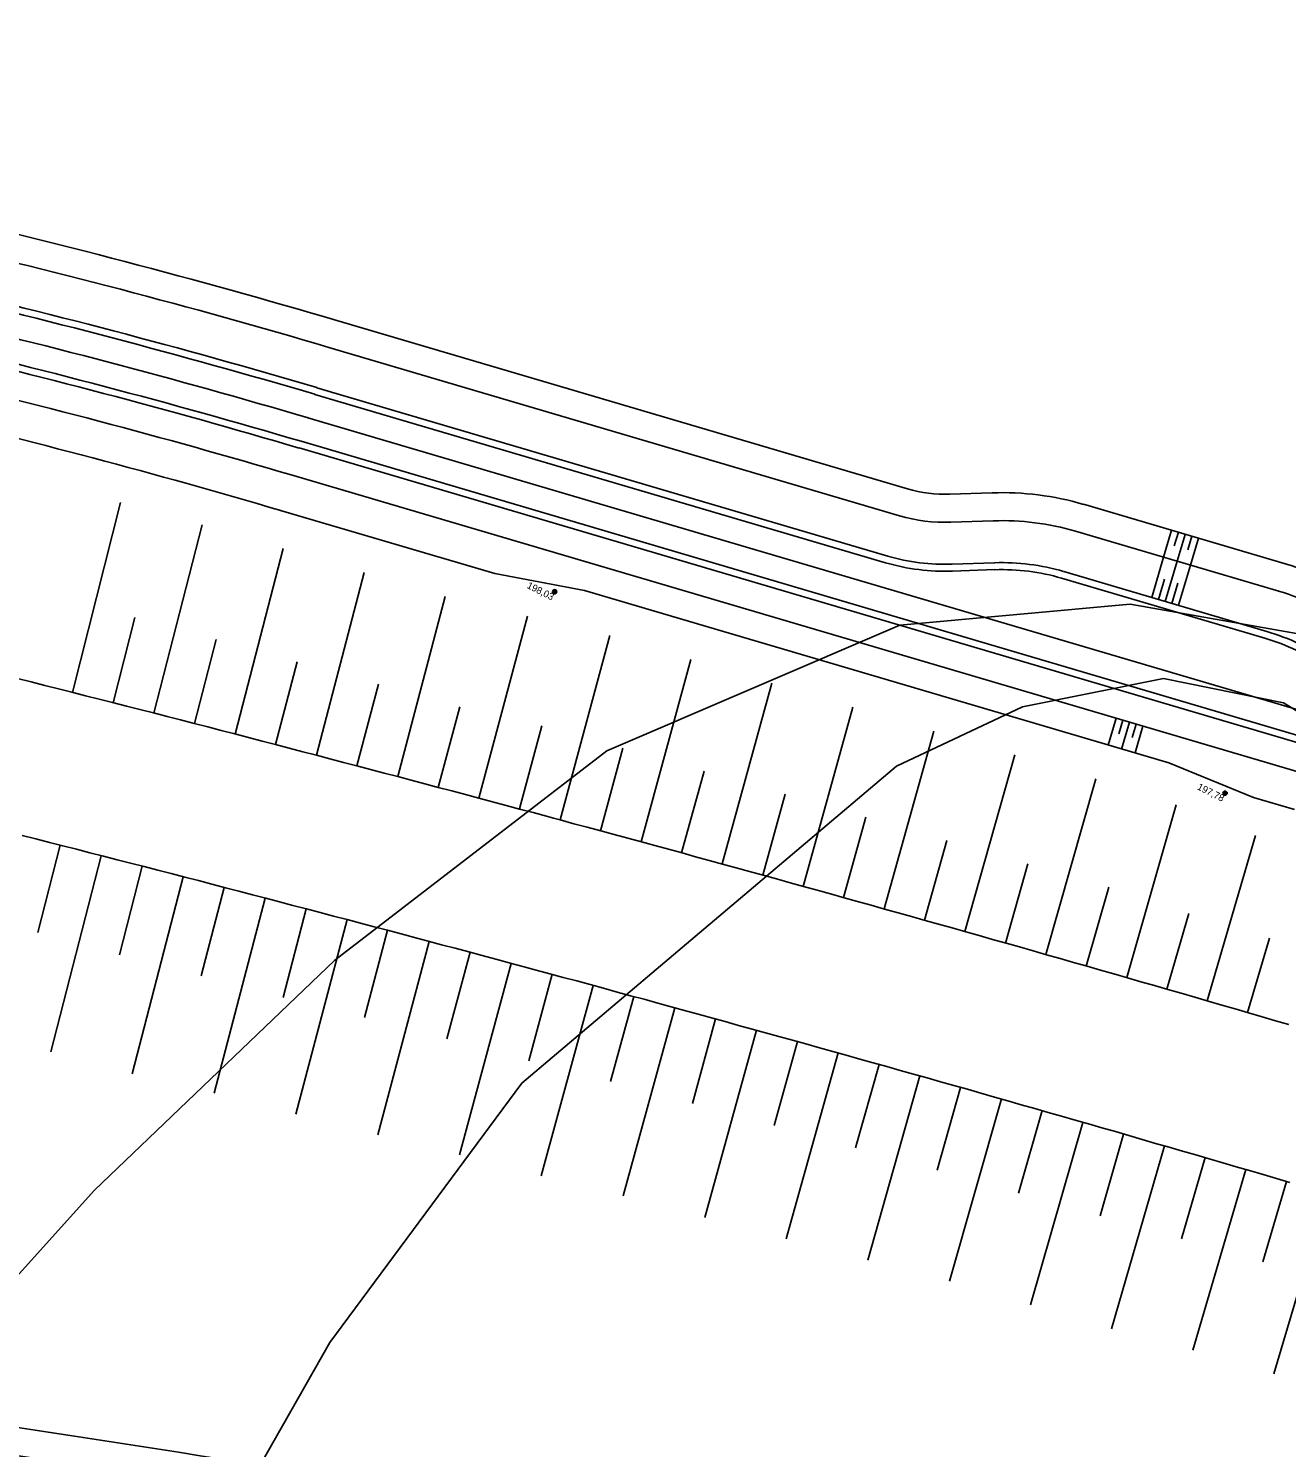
# Model space of a CAD drawing. Extents: x -551750 to -547457, y -1150683 to -1148508.
# Drawn here: x -551001.9 to -550912.1, y -1148784.8 to -1148683.4 of the extents above; entities that cross this region are included whole.
import ezdxf

# ---------------------------------------------------------------- set-up
doc = ezdxf.new("R2010")
doc.units = 0
for name, color, linetype in [('D02_ZaplUzemi20Vody', 7, 'Continuous'), ('D03_ZaplUzemi100Vody', 7, 'Continuous'), ('SO221815_VYSKOPIS', 7, 'Continuous'), ('u_trat navrh', 7, 'Continuous')]:
    doc.layers.add(name, color=color, linetype=linetype)

# ---------------------------------------------------------------- blocks, each defined once
blk = doc.blocks.new('SO221824_VYSKOPIS')
at = {"layer": 'SO221815_VYSKOPIS'}
for p, q in [((0.12, -0.09), (-0.12, 0.09)), ((0.09, 0.12), (-0.09, -0.12)), ((0.09, 0.12), (0, 0)), ((0, 0), (0.12, -0.09))]:
    blk.add_line(p, q, dxfattribs=at)
blk.add_lwpolyline([(-0.09, -0.12), (0, 0), (-0.12, 0.09)], dxfattribs=at)
blk.add_circle((0, 0), 0.15, dxfattribs=at)
for start, end in [(145.362, 235.1538), (325.362, 55.1538)]:
    blk.add_arc((0, 0), 0.15, start, end, dxfattribs=at)

msp = doc.modelspace()

# ---------------------------------------------------------------- linework, layer by layer
at = {"layer": 'D02_ZaplUzemi20Vody'}
msp.add_lwpolyline([(-551109.36, -1148705.24), (-551088.1, -1148709.36), (-551068.89, -1148720.34), (-551055.18, -1148738.19), (-551046.26, -1148762.89), (-551042.14, -1148808.19), (-551041.54, -1148830.24), (-551039.22, -1148846.5), (-551035.97, -1148860.35), (-551032.72, -1148862.74), (-551027.74, -1148863.09), (-551023.25, -1148861.46), (-551020.88, -1148856.92), (-551011.96, -1148833.58), (-551000.3, -1148812.31), (-550980.41, -1148777.31), (-550966.69, -1148758.78), (-550939.94, -1148736.13), (-550930.94, -1148731.89), (-550920.87, -1148729.87), (-550912.3, -1148731.6), (-550896.22, -1148741.39)], dxfattribs=at)
at = {"layer": 'D03_ZaplUzemi100Vody'}
msp.add_lwpolyline([(-551309.02, -1148785.89), (-551249.96, -1148750.74), (-551230.63, -1148737.06), (-551208, -1148722.96), (-551182.79, -1148711.42), (-551146.06, -1148694.75), (-551122.83, -1148687.16), (-551095.92, -1148683.42), (-551079.48, -1148686.41), (-551056.31, -1148700.62), (-551045.84, -1148714.09), (-551036.12, -1148737.27), (-551031.64, -1148755.22), (-551029.4, -1148770.93), (-551025.66, -1148778.41), (-551019.68, -1148783.65), (-551014.11, -1148783.92), (-551010.71, -1148781.4), (-550997.25, -1148766.44), (-550980.06, -1148749.99), (-550960.63, -1148735.03), (-550939.7, -1148726.05), (-550923.25, -1148724.56), (-550910.54, -1148726.8)], dxfattribs=at)
at = {"layer": 'u_trat navrh'}
for p, q in [((-550979.91, -1148704.29), (-550939.15, -1148716.32)), ((-550980.48, -1148706.21), (-550939.72, -1148718.24)), ((-550981.33, -1148709.09), (-550940.56, -1148721.12)), ((-550981.47, -1148709.57), (-550940.71, -1148721.6)), ((-550981.97, -1148711.25), (-550909.55, -1148732.61)), ((-550982.46, -1148712.92), (-550910.05, -1148734.29)), ((-550982.6, -1148713.4), (-550910.19, -1148734.77)), ((-550983.17, -1148715.32), (-550910.76, -1148736.69)), ((-550936.13, -1148716.7), (-550933.09, -1148716.6)), ((-550998.8, -1148730.86), (-550995.35, -1148717.29)), ((-550983.92, -1148717.86), (-550968.63, -1148722.37)), ((-550926.58, -1148717.42), (-550912.07, -1148721.71)), ((-550992.98, -1148732.34), (-550989.53, -1148718.9)), ((-550936.06, -1148718.7), (-550933.02, -1148718.6)), ((-550927.15, -1148719.34), (-550912.63, -1148723.62)), ((-550920.85, -1148721.2), (-550920.28, -1148719.28)), ((-550920.09, -1148720.38), (-550919.8, -1148719.42)), ((-550919.89, -1148721.48), (-550919.32, -1148719.57)), ((-550919.13, -1148720.67), (-550918.84, -1148719.71)), ((-550918.93, -1148721.77), (-550918.36, -1148719.85)), ((-550987.17, -1148733.84), (-550983.74, -1148720.59)), ((-550921.7, -1148724.08), (-550920.85, -1148721.2)), ((-550981.37, -1148735.35), (-550977.96, -1148722.29)), ((-550935.96, -1148721.7), (-550932.92, -1148721.6)), ((-550935.94, -1148722.2), (-550932.9, -1148722.09)), ((-550927.99, -1148722.22), (-550913.48, -1148726.5)), ((-550920.74, -1148724.36), (-550919.89, -1148721.48)), ((-550919.78, -1148724.64), (-550918.93, -1148721.77)), ((-550968.63, -1148722.37), (-550962.22, -1148723.59)), ((-550928.14, -1148722.7), (-550913.62, -1148726.98)), ((-550921.22, -1148724.22), (-550920.79, -1148722.78)), ((-550920.26, -1148724.5), (-550919.83, -1148723.06)), ((-550975.56, -1148736.88), (-550972.16, -1148724)), ((-550962.22, -1148723.59), (-550920.49, -1148735.9)), ((-550995.89, -1148731.6), (-550994.34, -1148725.52)), ((-550969.76, -1148738.42), (-550966.3, -1148725.42)), ((-550990.08, -1148733.09), (-550988.53, -1148727.08)), ((-550963.96, -1148739.97), (-550960.41, -1148726.79)), ((-550984.28, -1148734.59), (-550982.74, -1148728.67)), ((-550958.17, -1148741.54), (-550954.63, -1148728.5)), ((-550978.47, -1148736.11), (-550976.93, -1148730.28)), ((-550952.38, -1148743.12), (-550948.84, -1148730.21)), ((-550972.66, -1148737.65), (-550971.13, -1148731.89)), ((-550946.6, -1148744.72), (-550943.05, -1148731.91)), ((-550966.86, -1148739.19), (-550965.27, -1148733.25)), ((-550924.24, -1148732.71), (-550924.81, -1148734.63)), ((-550923.76, -1148732.85), (-550924.05, -1148733.81)), ((-550923.29, -1148732.99), (-550923.85, -1148734.91)), ((-550922.81, -1148733.13), (-550923.09, -1148734.09)), ((-550922.33, -1148733.28), (-550922.89, -1148735.19)), ((-550940.81, -1148746.33), (-550937.26, -1148733.62)), ((-550961.07, -1148740.75), (-550959.47, -1148734.85)), ((-550935.04, -1148747.95), (-550931.48, -1148735.33)), ((-550955.28, -1148742.33), (-550953.68, -1148736.49)), ((-550920.49, -1148735.9), (-550914.44, -1148738.36)), ((-550929.26, -1148749.59), (-550925.69, -1148737.04)), ((-550949.49, -1148743.92), (-550947.89, -1148738.13)), ((-550914.44, -1148738.36), (-550911.51, -1148739.23)), ((-550923.49, -1148751.24), (-550919.95, -1148738.89)), ((-550943.71, -1148745.52), (-550942.11, -1148739.78)), ((-550937.93, -1148747.14), (-550936.33, -1148741.44)), ((-550917.73, -1148752.9), (-550914.3, -1148741.08)), ((-550999.68, -1148741.78), (-551001.27, -1148748.01)), ((-550996.75, -1148742.53), (-551000.33, -1148756.54)), ((-550993.81, -1148743.28), (-550995.44, -1148749.62)), ((-550932.15, -1148748.77), (-550930.55, -1148743.1)), ((-550990.88, -1148744.03), (-550994.52, -1148758.11)), ((-550987.95, -1148744.8), (-550989.59, -1148751.1)), ((-550985.02, -1148745.56), (-550988.66, -1148759.5)), ((-550926.38, -1148750.41), (-550924.77, -1148744.78)), ((-550982.09, -1148746.33), (-550983.75, -1148752.66)), ((-550979.17, -1148747.09), (-550982.84, -1148761)), ((-550920.61, -1148752.07), (-550919.05, -1148746.65)), ((-550976.28, -1148747.86), (-550977.93, -1148754.09)), ((-550973.31, -1148748.65), (-550976.99, -1148762.46)), ((-550914.85, -1148753.74), (-550913.3, -1148748.43)), ((-550970.38, -1148749.43), (-550972.04, -1148755.62)), ((-550967.46, -1148750.22), (-550971.15, -1148763.91)), ((-550964.53, -1148751), (-550966.2, -1148757.18)), ((-550961.61, -1148751.8), (-550965.31, -1148765.39)), ((-550958.69, -1148752.59), (-550960.35, -1148758.66)), ((-550955.77, -1148753.39), (-550959.45, -1148766.82)), ((-550952.85, -1148754.19), (-550954.51, -1148760.23)), ((-550949.93, -1148755), (-550953.63, -1148768.37)), ((-550947.01, -1148755.81), (-550948.68, -1148761.8)), ((-550944.1, -1148756.62), (-550947.81, -1148769.9)), ((-550941.18, -1148757.44), (-550942.86, -1148763.41)), ((-550938.26, -1148758.26), (-550941.98, -1148771.43)), ((-550935.35, -1148759.09), (-550937.03, -1148765)), ((-550932.44, -1148759.91), (-550936.14, -1148772.93)), ((-550929.53, -1148760.74), (-550931.21, -1148766.64)), ((-550926.62, -1148761.58), (-550930.36, -1148774.62)), ((-550923.71, -1148762.42), (-550925.39, -1148768.26)), ((-550920.8, -1148763.26), (-550924.58, -1148776.32)), ((-550917.89, -1148764.1), (-550919.58, -1148769.9)), ((-550914.98, -1148764.95), (-550918.76, -1148777.86)), ((-550912.08, -1148765.8), (-550913.76, -1148771.55)), ((-550909.17, -1148766.66), (-550912.97, -1148779.54))]:
    msp.add_line(p, q, dxfattribs=at)
for points in [[(-551002.71, -1148729.87), (-551001.74, -1148730.11), (-551000.77, -1148730.36), (-550999.8, -1148730.6), (-550998.83, -1148730.85), (-550997.86, -1148731.1), (-550996.89, -1148731.34), (-550995.92, -1148731.59), (-550994.94, -1148731.84), (-550993.97, -1148732.09), (-550993, -1148732.33), (-550992.03, -1148732.58), (-550991.07, -1148732.83), (-550990.1, -1148733.08), (-550989.13, -1148733.33), (-550988.16, -1148733.58), (-550987.19, -1148733.83), (-550986.22, -1148734.09), (-550985.25, -1148734.34), (-550984.28, -1148734.59), (-550983.31, -1148734.84), (-550982.34, -1148735.1), (-550981.37, -1148735.35), (-550980.4, -1148735.6), (-550979.44, -1148735.86), (-550978.47, -1148736.11), (-550977.5, -1148736.37), (-550976.53, -1148736.62), (-550975.56, -1148736.88), (-550974.59, -1148737.13), (-550973.63, -1148737.39), (-550972.66, -1148737.65), (-550971.69, -1148737.9), (-550970.72, -1148738.16), (-550969.76, -1148738.42), (-550968.79, -1148738.68), (-550967.82, -1148738.94), (-550966.85, -1148739.2), (-550965.89, -1148739.45), (-550964.92, -1148739.71), (-550964.43, -1148739.85), (-550963.95, -1148739.97), (-550962.99, -1148740.24), (-550962.02, -1148740.5), (-550961.05, -1148740.76), (-550960.09, -1148741.02), (-550959.12, -1148741.28), (-550958.15, -1148741.54), (-550957.19, -1148741.81), (-550956.22, -1148742.07), (-550955.25, -1148742.33), (-550954.29, -1148742.6), (-550953.32, -1148742.86), (-550952.36, -1148743.13), (-550951.39, -1148743.39), (-550950.43, -1148743.66), (-550949.46, -1148743.93), (-550948.5, -1148744.19), (-550947.53, -1148744.46), (-550946.57, -1148744.73), (-550945.6, -1148744.99), (-550944.64, -1148745.26), (-550943.67, -1148745.53), (-550942.71, -1148745.8), (-550941.74, -1148746.07), (-550940.78, -1148746.34), (-550939.81, -1148746.61), (-550938.85, -1148746.88), (-550937.88, -1148747.15), (-550936.92, -1148747.42), (-550935.96, -1148747.69), (-550934.99, -1148747.96), (-550934.03, -1148748.23), (-550933.07, -1148748.51), (-550932.1, -1148748.78), (-550931.14, -1148749.05), (-550930.18, -1148749.33), (-550929.21, -1148749.6), (-550928.25, -1148749.88), (-550927.29, -1148750.15), (-550926.32, -1148750.43), (-550925.36, -1148750.7), (-550924.4, -1148750.98), (-550923.44, -1148751.25), (-550922.47, -1148751.53), (-550921.51, -1148751.81), (-550920.55, -1148752.09), (-550919.59, -1148752.36), (-550918.63, -1148752.64), (-550917.66, -1148752.92), (-550916.7, -1148753.2), (-550915.74, -1148753.48), (-550914.78, -1148753.76), (-550913.82, -1148754.04), (-550912.86, -1148754.32), (-550911.9, -1148754.6)], [(-551002.38, -1148741.09), (-551001.41, -1148741.33), (-551000.44, -1148741.58), (-550999.48, -1148741.83), (-550998.51, -1148742.07), (-550997.54, -1148742.32), (-550996.57, -1148742.57), (-550995.61, -1148742.82), (-550994.64, -1148743.07), (-550993.67, -1148743.31), (-550992.7, -1148743.56), (-550991.74, -1148743.81), (-550990.77, -1148744.06), (-550989.8, -1148744.31), (-550988.84, -1148744.56), (-550987.87, -1148744.82), (-550986.9, -1148745.07), (-550985.94, -1148745.32), (-550984.97, -1148745.57), (-550984, -1148745.82), (-550983.04, -1148746.08), (-550982.07, -1148746.33), (-550981.11, -1148746.58), (-550980.14, -1148746.84), (-550979.17, -1148747.09), (-550978.21, -1148747.35), (-550977.24, -1148747.6), (-550976.28, -1148747.86), (-550975.31, -1148748.12), (-550974.35, -1148748.37), (-550973.38, -1148748.63), (-550972.42, -1148748.89), (-550971.45, -1148749.14), (-550970.49, -1148749.4), (-550969.52, -1148749.66), (-550968.56, -1148749.92), (-550967.59, -1148750.18), (-550967.53, -1148750.2), (-550966.63, -1148750.44), (-550965.67, -1148750.7), (-550964.7, -1148750.96), (-550963.74, -1148751.22), (-550962.77, -1148751.48), (-550961.81, -1148751.74), (-550960.85, -1148752), (-550959.88, -1148752.27), (-550958.92, -1148752.53), (-550957.96, -1148752.79), (-550956.99, -1148753.06), (-550956.03, -1148753.32), (-550955.07, -1148753.58), (-550954.1, -1148753.85), (-550953.14, -1148754.11), (-550952.18, -1148754.38), (-550951.21, -1148754.65), (-550950.25, -1148754.91), (-550949.29, -1148755.18), (-550948.33, -1148755.45), (-550947.36, -1148755.71), (-550946.4, -1148755.98), (-550945.44, -1148756.25), (-550944.48, -1148756.52), (-550943.52, -1148756.79), (-550942.55, -1148757.06), (-550941.59, -1148757.32), (-550940.63, -1148757.59), (-550939.67, -1148757.87), (-550938.71, -1148758.14), (-550937.75, -1148758.41), (-550936.79, -1148758.68), (-550935.83, -1148758.95), (-550934.86, -1148759.22), (-550933.9, -1148759.5), (-550932.94, -1148759.77), (-550931.98, -1148760.04), (-550931.02, -1148760.32), (-550930.06, -1148760.59), (-550929.1, -1148760.87), (-550928.14, -1148761.14), (-550927.18, -1148761.42), (-550926.22, -1148761.69), (-550925.26, -1148761.97), (-550924.3, -1148762.24), (-550923.34, -1148762.52), (-550922.38, -1148762.8), (-550921.42, -1148763.08), (-550920.46, -1148763.35), (-550919.51, -1148763.63), (-550918.55, -1148763.91), (-550917.59, -1148764.19), (-550916.63, -1148764.47), (-550915.67, -1148764.75), (-550914.71, -1148765.03), (-550913.75, -1148765.31), (-550912.79, -1148765.59), (-550911.84, -1148765.87)]]:
    msp.add_lwpolyline(points, dxfattribs=at)
for centre, radius, start, end in [((-551123.48, -1149190.8), 507.25, 73.559, 77.1071), ((-551123.48, -1149190.8), 505.25, 73.559, 77.0641), ((-551123.48, -1149190.8), 501.75, 73.559, 76.9876), ((-551123.48, -1149190.8), 502.25, 73.559, 76.9988), ((-551123.48, -1149190.8), 500, 73.559, 76.9491), ((-551123.48, -1149190.8), 497.75, 73.559, 76.8993), ((-551123.48, -1149190.8), 498.25, 73.559, 76.9104), ((-551123.48, -1149190.8), 495.75, 73.559, 76.8546), ((-551123.48, -1149190.8), 493.1, 73.559, 76.7949), ((-550936.46, -1148707.21), 9.5, 253.559, 271.994), ((-550932.38, -1148737.09), 20.5, 73.559, 91.994), ((-550936.46, -1148707.21), 11.5, 253.559, 271.994), ((-550932.38, -1148737.09), 18.5, 73.559, 91.994), ((-550936.46, -1148707.21), 14.5, 253.559, 271.994), ((-550936.46, -1148707.21), 15, 253.559, 271.994), ((-550932.38, -1148737.09), 15.5, 73.559, 91.994), ((-550932.38, -1148737.09), 15, 73.559, 91.994), ((-550917.87, -1148741.37), 20.5, 55.1241, 73.559), ((-550917.87, -1148741.37), 18.5, 55.1241, 73.559), ((-550917.87, -1148741.37), 15, 55.1241, 73.559), ((-550917.87, -1148741.37), 15.5, 55.1241, 73.559), ((-551226.7, -1150272.63), 1504, 76.89047, 82.52854), ((-551226.7, -1150272.63), 1503.25, 76.89047, 82.52854), ((-551226.7, -1150272.63), 1506, 77.72157, 81.54129)]:
    msp.add_arc(centre, radius, start, end, dxfattribs=at)

# ---------------------------------------------------------------- block references
at = {"layer": 'u_trat navrh', "rotation": -31.851985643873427}
for p in [(-550964.35, -1148723.67), (-550916.46, -1148738.06)]:
    msp.add_blockref('SO221824_VYSKOPIS', p, dxfattribs=at)

# ---------------------------------------------------------------- texts
at = {"layer": 'u_trat navrh'}
for s, p in [('198,03', (-550966.38, -1148723.38)), ('197,78', (-550918.5, -1148737.77))]:
    msp.add_text(s, height=0.5, rotation=333.2568, dxfattribs=at).set_placement(p)

doc.saveas('drawing.dxf')
